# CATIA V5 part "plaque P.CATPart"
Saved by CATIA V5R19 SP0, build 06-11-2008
Part number: plaque P
Bounding box of the stored display mesh (mm): x 0 to 300, y 0 to 250, z 0 to 40
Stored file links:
  C:\Users\Hicham57\Desktop\Chassis presse\plaque P.CATPart
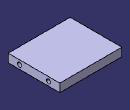
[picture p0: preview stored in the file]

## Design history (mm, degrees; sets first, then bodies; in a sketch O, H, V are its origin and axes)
Body1 (main body)
  Sketch1 on yz-plane, origin (0, 0, 0), H (0, 1, 0), V (0, 0, 1)
    line L1 (0, 0) -> (250, 0)
    line L2 (250, 0) -> (250, 40)
    line L3 (250, 40) -> (0, 40)
    line L4 (0, 40) -> (0, 0)
    length L2 = 40
    length L3 = 250
    horizontal: L1 H, L3 H
    vertical: L2 V, L4 V
  Pad1: profile Sketch1, direction (1, 0, 0), length 300
  Sketch2 on end face of Pad1, origin (300, 0, 0), H (0, 1, 0), V (0, 0, 1)
    circle A1 centre (55, 20) radius 10
    point P1 (55, 20)
    circle A2 centre (195, 20) radius 10
    point P2 (195, 20)
    reference projected line E1 (0, 40) -> (0, 0) from edge [face of Pad1 from Sketch1.L4 | end face of Pad1]
    reference projected line E2 (0, 0) -> (250, 0) from edge [face of Pad1 from Sketch1.L1 | end face of Pad1]
    reference projected line E3 (0, 0) -> (250, 0) from edge [face of Pad1 from Sketch1.L1 | end face of Pad1]
    radius A2 = 10
    radius A1 = 10
    distance E1 P1 = 55
    distance P1 E2 = 20
    distance P2 E3 = 20
    distance P1 P2 = 140
  Pocket1: profile Sketch2, direction (-1, 0, 0), length 50
  Thread1: diameter 22, depth 50, pitch 1, on face of Pocket1 from Sketch2.A2, from end face of Pad1
  Thread2: diameter 22, depth 50, pitch 1, on face of Pocket1 from Sketch2.A1, from end face of Pad1
  Sketch3 on start face of Pad1, origin (0, 0, 0), H (0, -1, 0), V (0, 0, 1)
    circle A1 centre (-55, 20) radius 10
    circle A2 centre (-195, 20) radius 10
    reference projected circle E1 centre (-195, 20) radius 10 from edge [face of Pocket1 from Sketch2.A2 | end face of Pocket1]
    reference projected circle E2 centre (-55, 20) radius 10 from edge [face of Pocket1 from Sketch2.A1 | end face of Pocket1]
    coincidence: A2 E1, A1 E2
  Pocket2: profile Sketch3, direction (1, 0, 0), length 50
  Thread3: diameter 22, depth 50, pitch 1, on face of Pocket2 from Sketch3.A1, from start face of Pad1
  Thread4: diameter 22, depth 50, pitch 1, on face of Pocket2 from Sketch3.A2, from start face of Pad1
